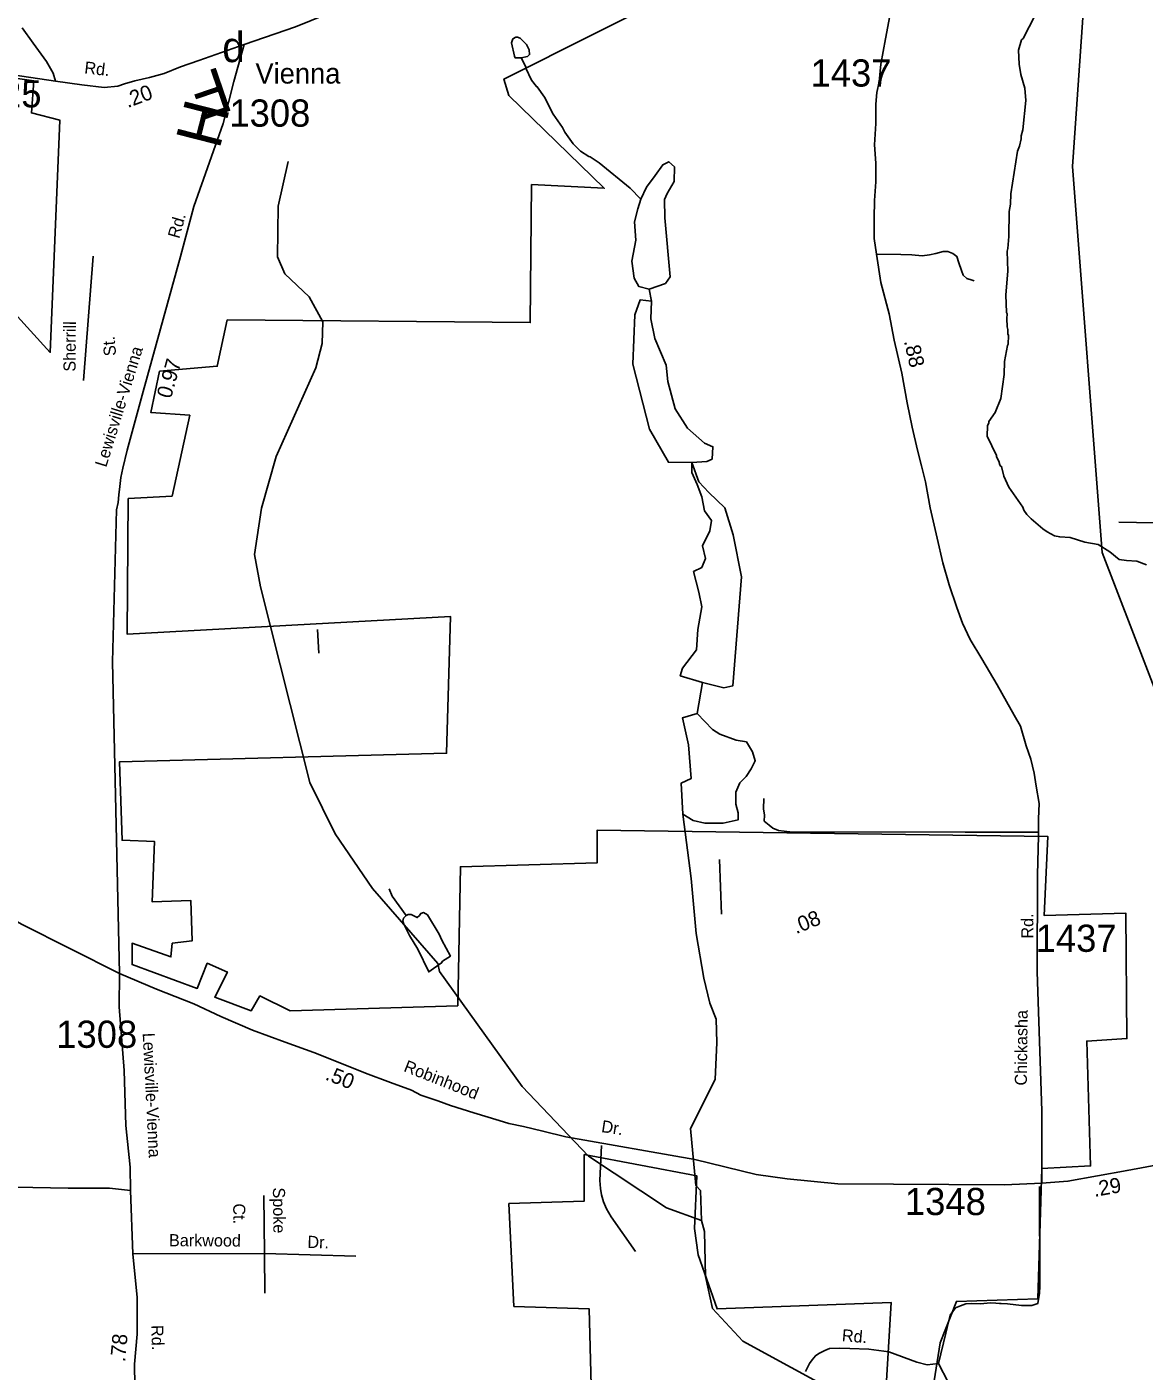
# Model space of a CAD drawing. Extents: x 1551653 to 1702041, y 811336 to 920032.
# Drawn here: x 1584838 to 1590899, y 864750 to 872044 of the extents above; entities that cross this region are included whole.
import ezdxf

# ---------------------------------------------------------------- set-up
doc = ezdxf.new("R2010")
doc.units = 0
for name, color, linetype in [('Old_Level_10', 7, 'Continuous'), ('Old_Level_11', 7, 'Continuous'), ('Old_Level_17', 7, 'Continuous'), ('Old_Level_22', 7, 'Continuous'), ('Old_Level_32', 7, 'Continuous'), ('Old_Level_35', 7, 'Continuous'), ('Old_Level_48', 7, 'Continuous'), ('Old_Level_49', 7, 'Continuous'), ('Old_Level_56', 7, 'Continuous'), ('Old_Level_59', 7, 'Continuous'), ('Old_Level_62', 7, 'Continuous'), ('Old_Level_8', 7, 'Continuous'), ('Old_Level_9', 7, 'Continuous')]:
    doc.layers.add(name, color=color, linetype=linetype)

msp = doc.modelspace()

# ---------------------------------------------------------------- linework, layer by layer
at = {"layer": 'Old_Level_32'}
for points in [[(1589631.53, 873556.503), (1589549.907, 873543.938), (1589452.588, 873515.667), (1589358.408, 873487.396), (1589251.671, 873459.125), (1589148.073, 873424.571), (1589050.754, 873393.159), (1588956.574, 873355.464), (1588906.344, 873333.475), (1588812.164, 873289.498), (1588680.312, 873229.815), (1588520.207, 873163.849), (1588247.085, 873019.352), (1587075.046, 872402.399), (1586766.222, 872241.655), (1586541.733, 872143.369), (1586294.795, 872045.084), (1586016.988, 871949.607)], [(1589524.792, 872134.153), (1589496.539, 871980.232), (1589471.424, 871841.389), (1589462.006, 871747.152), (1589449.449, 871687.469), (1589443.17, 871624.644), (1589443.17, 871520.984), (1589436.891, 871404.758), (1589443.17, 871304.238), (1589443.17, 871203.719), (1589436.891, 871103.199), (1589433.752, 871006.45), (1589433.752, 870896.507), (1589446.309, 870811.693), (1589471.424, 870657.773), (1589515.375, 870488.146), (1589543.628, 870343.649), (1589584.44, 870164.599), (1589612.694, 870004.396), (1589640.948, 869872.464), (1589669.202, 869746.815), (1589691.177, 869662.001), (1589713.152, 869575.304), (1589738.267, 869433.948), (1589775.939, 869270.604), (1589807.333, 869135.531), (1589841.865, 869016.164), (1589882.676, 868893.656), (1589914.07, 868808.843), (1589954.881, 868720.888), (1590017.874, 868614.474), (1590101.559, 868473.88), (1590152.367, 868384.141), (1590194.209, 868309.357), (1590228.003, 868249.703), (1590259.396, 868142.901), (1590284.511, 868070.653), (1590303.347, 867995.263), (1590313.76, 867923.474), (1590329.034, 867830.712), (1590326.413, 867747.814), (1590326.413, 867654.947), (1590321.169, 867442.456), (1590318.548, 866916.212), (1590343.341, 866162.929), (1590344.249, 865770.137)], [(1584812.467, 872039.529), (1584872.506, 871956.569), (1584943.98, 871856.444), (1584981.146, 871793.509), (1584992.581, 871750.598)], [(1584992.581, 871750.598), (1584393.664, 871838.227), (1584285.14, 871854.792), (1584147.187, 871875.037), (1584023.948, 871889.762), (1583922.782, 871878.719), (1583836.331, 871845.589)], [(1586016.988, 871949.607), (1585770.05, 871862.553), (1585670.491, 871826.79), (1585581.736, 871791.805), (1585503.468, 871769.884), (1585423.535, 871750.987), (1585367.054, 871734.84), (1585331.83, 871723.556), (1585256.783, 871716.001), (1585135.529, 871730.573), (1584992.581, 871750.598)], [(1585340.18, 866907.445), (1585302.146, 868599.351), (1585324.563, 869423.569), (1585332.593, 869463.914), (1585337.193, 869505.912), (1585341.758, 869549.74), (1585347.489, 869598.488), (1585358.952, 869650.104), (1585381.878, 869747.601), (1585467.852, 870065.897), (1585671.383, 870797.696), (1585743.589, 871070.118), (1585901.938, 871519.958), (1585960.866, 871747.419), (1586016.988, 871949.607)], [(1592540.685, 869172.234), (1591327.918, 869167.855), (1591294.317, 869161.873), (1591268.116, 869164.173), (1591239.647, 869167.855), (1591195.512, 869202.727), (1591160.667, 869239.925), (1591121.178, 869286.421), (1591065.428, 869330.592), (1591009.139, 869346.365), (1590953.037, 869353.366), (1590761.125, 869356.165)], [(1585340.18, 866907.445), (1584809.002, 867175.902), (1584482.046, 867364.242), (1584264.296, 867492.423), (1583970.754, 867637.718), (1583880.933, 867696.925), (1583104.211, 868113.539), (1582470.483, 868439.25), (1582201.154, 868514.025), (1581671.411, 868518.925), (1581185.495, 868552.46)], [(1585520.127, 862781.948), (1585480.764, 863151.475), (1585441.395, 863438.722), (1585414.958, 863618.062), (1585426.805, 863875.742), (1585426.805, 863963.941), (1585426.883, 864438.463), (1585421.009, 864788.322), (1585435.695, 864950.021), (1585435.695, 865149.94), (1585412.372, 865386.502), (1585400.072, 865730.182), (1585397.684, 865856.901), (1585374.243, 866082.327), (1585365.43, 866382.206), (1585338.994, 866726.185), (1585340.18, 866907.445)], [(1590344.249, 865770.137), (1590142.272, 865761.564), (1589237.766, 865766.959), (1588962.084, 865792.897), (1588793.612, 865817.655), (1588461.008, 865897.951), (1587760.88, 866022.283), (1587637.835, 866053.071), (1587531.879, 866077.017), (1587453.266, 866094.121), (1587399.546, 866110.721), (1587262.829, 866151.771), (1587135.296, 866191.711), (1587067.796, 866216.71), (1586975.723, 866247.555), (1586924.454, 866274.922), (1586810.285, 866316.751), (1586674.885, 866366.951), (1586545.386, 866420.071), (1586394.087, 866478.372), (1586239.097, 866534.571), (1586061.364, 866599.567), (1585890.467, 866674.826), (1585743.496, 866743.243), (1585541.838, 866821.923), (1585340.18, 866907.445)], [(1591826.318, 866036.569), (1591529.518, 865984.87), (1591252.717, 865930.867), (1591063.918, 865889.47), (1590991.52, 865872.57), (1590806.917, 865839.269), (1590486.019, 865779.968), (1590344.249, 865770.137)]]:
    msp.add_lwpolyline(points, dxfattribs=at)
at = {"layer": 'Old_Level_35'}
for p, q in [((1585198.009, 870800.015), (1585144.53, 870125.462)), ((1586421.957, 868645.306), (1586413.778, 868773.529)), ((1589927.465, 867675.29), (1590326.413, 867674.714)), ((1588605.434, 867228.875), (1588595.819, 867525.737)), ((1586126.428, 865388.768), (1586122.927, 865702.971)), ((1585412.372, 865386.502), (1586126.428, 865388.768)), ((1586126.428, 865388.768), (1586622.428, 865373.67)), ((1586126.428, 865388.768), (1586129.23, 865172.571))]:
    msp.add_line(p, q, dxfattribs=at)
for points in [[(1589446.309, 870811.693), (1589578.521, 870809.558), (1589638.721, 870806.76), (1589694.721, 870802.058), (1589734.62, 870807.458), (1589768.822, 870814.958), (1589809.022, 870826.359), (1589835.02, 870826.057), (1589860.82, 870815.46), (1589882.72, 870799.26), (1589894.222, 870764.958), (1589907.621, 870722.859), (1589917.319, 870696.658), (1589936.919, 870678.459), (1589966.722, 870669.86), (1589976.722, 870665.858)], [(1588835.524, 867856.864), (1588834.723, 867800.863), (1588840.323, 867766.664), (1588837.823, 867734.666), (1588865.422, 867712.366), (1588885.323, 867696.165), (1588915.021, 867683.764), (1588976.921, 867676.664), (1589927.465, 867675.29)], [(1587955.703, 865974.391), (1587946.825, 865784.568), (1587950.325, 865740.671), (1587955.824, 865706.468), (1587965.325, 865668.269), (1587982.723, 865629.87), (1588008.124, 865587.571), (1588139.324, 865399.569)], [(1585400.072, 865730.182), (1585286.584, 865743.544), (1585061.832, 865743.544), (1584581.175, 865752.452), (1584289.665, 865759.133), (1584169.501, 865759.133), (1584064.914, 865776.949), (1583973.678, 865808.127), (1583877.991, 865828.17), (1583780.079, 865834.851), (1583556.736, 865834.789), (1583552.285, 865520.781), (1583550.06, 865487.376), (1583542.332, 865476.37)], [(1590331.748, 865752.053), (1590333.875, 865211.354), (1590331.748, 865173.037), (1590322.573, 865117.126), (1590290.572, 865105.728), (1590233.91, 865107.046), (1590157.341, 865115.561), (1590114.977, 865117.062)], [(1590123.311, 865117.69), (1590065.884, 865119.819), (1590010.591, 865114.369), (1589962.319, 865117.171), (1589931.895, 865114.369), (1589902.118, 865103.726), (1589876.595, 865093.082), (1589847.653, 865053.963), (1589837.155, 865017.962), (1589823.423, 864956.843), (1589783.011, 864790.801)], [(1589783.011, 864790.801), (1589721.331, 864784.415), (1589666.03, 864799.317), (1589514.121, 864855.472), (1589406.323, 864869.071), (1589302.321, 864872.572), (1589246.323, 864875.272), (1589192.321, 864872.172), (1589166.022, 864862.572), (1589133.922, 864844.97), (1589115.621, 864833.369), (1589097.423, 864811.47), (1589083.023, 864791.772), (1589062.521, 864747.972)], [(1589783.011, 864790.801), (1589835.344, 864689.735), (1589861.74, 864593.941), (1589921.293, 864404.484), (1589902.151, 864125.619), (1589906.428, 864011.922), (1590006.393, 863794.791), (1590057.439, 863664.938), (1590063.82, 863496.768), (1590076.582, 863392.46), (1590176.216, 863285.178), (1590237.671, 863209.285), (1590316.254, 863010.556), (1590340.567, 862868.477), (1590369.936, 862772.029), (1590391.697, 862707.804)]]:
    msp.add_lwpolyline(points, dxfattribs=at)
at = {"layer": 'Old_Level_48'}
msp.add_lwpolyline([(1583701.392, 871667.226), (1584964.915, 870278.066), (1585016.322, 871538.633), (1584862.103, 871577.222), (1584876.433, 871751.032), (1584206.67, 871847.344), (1583955.379, 871865.566), (1583838.154, 871812.489), (1583701.392, 871667.226)], dxfattribs=at)
at = {"layer": 'Old_Level_49'}
for points in [[(1588412.049, 872257.625), (1587425.971, 871760.749), (1587453.173, 871672.264), (1587970.014, 871168.581), (1587575.583, 871189), (1587568.782, 870440.281), (1585925.133, 870454.707), (1585870.729, 870202.866), (1585557.904, 870175.64), (1585510.3, 869951.024), (1585721.117, 869937.411), (1585625.871, 869498.667), (1585387.853, 869485.054), (1585381.052, 868749.949), (1587135.591, 868845.24), (1587115.189, 868103.328), (1585340.248, 868055.682), (1585354.076, 867630.363), (1585530.89, 867623.556), (1585517.289, 867296.843), (1585728.106, 867303.649), (1585734.906, 867085.84), (1585626.098, 867072.227), (1585619.297, 866997.355), (1585408.481, 867072.227), (1585408.481, 866956.516), (1585762.109, 866827.192), (1585816.513, 866963.322), (1585925.321, 866915.676), (1585857.316, 866779.546), (1586054.532, 866704.675), (1586102.136, 866786.353), (1586265.348, 866704.675), (1587176.62, 866731.901)], [(1583701.392, 871667.226), (1584964.915, 870278.066), (1585016.322, 871538.633), (1584862.103, 871577.222), (1584876.433, 871751.032), (1584206.67, 871847.344), (1583955.379, 871865.566), (1583838.154, 871812.489), (1583701.392, 871667.226)], [(1587176.62, 866731.901), (1587190.222, 867487.426), (1587931.48, 867507.845), (1587931.48, 867684.815), (1590377.458, 867650.782), (1590357.056, 867221.971), (1590799.091, 867235.584), (1590805.891, 866554.931), (1590588.274, 866541.318), (1590608.729, 865863.804), (1590343.508, 865850.191), (1590323.106, 865142.312), (1589881.071, 865128.699), (1589792.664, 864904.084), (1589724.659, 864468.466)], [(1589486.64, 864454.853), (1589527.443, 865121.892), (1588582.169, 865087.86), (1588480.16, 865380.541), (1588459.759, 865523.478), (1588473.36, 865809.352), (1587861.311, 865925.063), (1587861.311, 865673.222), (1587453.279, 865659.609), (1587480.481, 865101.473), (1587888.514, 865087.86), (1587905.959, 864395.515)]]:
    msp.add_lwpolyline(points, dxfattribs=at)
at = {"layer": 'Old_Level_56'}
msp.add_lwpolyline([(1594795.417, 882224.158), (1594492.304, 881911.724), (1594314.227, 881725.829), (1594181.696, 881585.23), (1591756.719, 879036.343), (1591646.319, 875141.951), (1590597.318, 874408.75), (1590660.92, 873411.252), (1590633.821, 873059.655), (1590510.018, 871286.457), (1590671.819, 869193.062), (1591400.592, 867299.426), (1591680.416, 866598.966), (1590226.62, 861827.778), (1590099.721, 859136.383), (1590298.021, 857488.686)], dxfattribs=at)
at = {"layer": 'Old_Level_59'}
for points in [[(1586712.194, 867369.185), (1586510.525, 867665.178), (1586372.525, 867943.741), (1586104.522, 869006.219), (1586073.559, 869180.82), (1586110.571, 869432.829), (1586189.516, 869713.648), (1586405.538, 870195.11), (1586440.5, 870325.626), (1586442.55, 870443.839), (1586369.552, 870579.891), (1586237.498, 870704.05), (1586197.513, 870796.733), (1586201.511, 871072.426), (1586254.517, 871314.285)], [(1588442.593, 867423.517), (1588397.016, 867772.164), (1588387.441, 867939.89), (1588442.501, 867966.247), (1588428.138, 868148.35), (1588394.622, 868294.511), (1588473.623, 868318.471), (1588502.451, 868487.412)], [(1588497.582, 865566.572), (1588307.601, 865636.085), (1587885.604, 865917.109), (1587524.508, 866295.43), (1587075.546, 866918.378), (1587067.549, 866961.234), (1586712.194, 867369.185)], [(1588497.582, 865566.572), (1588491.533, 865730.819), (1588467.542, 865757.578), (1588438.527, 866066.797), (1588571.849, 866331.883), (1588581.425, 866533.154), (1588576.637, 866660.147), (1588543.122, 866746.406), (1588509.606, 866882.983), (1588468.927, 867124.007), (1588442.593, 867423.517)], [(1591114.559, 863734.329), (1591039.613, 863768.573), (1590719.527, 864100.142), (1590611.567, 864151.508), (1590020.607, 864193.031), (1589771.571, 864270.336), (1589498.544, 864433.455), (1589246.74, 864627.229), (1588721.602, 864912.046), (1588557.56, 865089.416), (1588518.6, 865264.121), (1588513.576, 865507.107), (1588497.582, 865566.572)]]:
    msp.add_lwpolyline(points, dxfattribs=at)
at = {"layer": 'Old_Level_62'}
msp.add_line((1588213.092, 870620.463), (1588227.412, 870556.688), dxfattribs=at)
for points in [[(1590911.66, 869124.944), (1590859.885, 869145.654), (1590804.008, 869148.32), (1590764.023, 869154.881), (1590712.555, 869195.482), (1590648.989, 869236.287), (1590577.22, 869249.205), (1590497.455, 869274.324), (1590441.476, 869276.99), (1590413.589, 869283.346), (1590373.809, 869303.852), (1590350.023, 869320.153), (1590286.662, 869375.005), (1590262.978, 869399.303), (1590247.292, 869421.449), (1590241.448, 869437.546), (1590164.758, 869546.531), (1590137.486, 869606.919), (1590126.106, 869659.002), (1590120.159, 869661.155), (1590116.263, 869667.204), (1590110.419, 869687.299), (1590098.731, 869711.393), (1590098.834, 869719.39), (1590048.084, 869824.069), (1590048.801, 869880.048), (1590057.003, 869895.94), (1590057.106, 869903.937), (1590091.657, 869951.509), (1590122.62, 870027.07), (1590140.152, 870158.816), (1590140.972, 870228.842), (1590158.094, 870314.656), (1590162.195, 870322.55), (1590162.708, 870370.533), (1590158.812, 870378.632), (1590159.119, 870402.623), (1590155.326, 870416.669), (1590153.89, 870462.703), (1590156.146, 870486.695), (1590152.25, 870494.692), (1590149.379, 870590.758), (1590158.914, 870718.608), (1590156.248, 870826.671), (1590160.452, 870842.562), (1590165.168, 870906.539), (1590166.911, 871042.488), (1590173.37, 871082.473), (1590176.036, 871138.35), (1590212.843, 871369.956), (1590223.198, 871397.741), (1590231.605, 871437.726), (1590231.81, 871453.72), (1590240.217, 871485.606), (1590258.159, 871645.341), (1590251.393, 871712.496), (1590230.99, 871786.11), (1590220.532, 871841.781), (1590217.457, 871917.856), (1590234.168, 871973.63), (1590242.268, 871981.524), (1590307.782, 872108.657)], [(1587519.176, 871876.435), (1587552.907, 871884.125), (1587565.108, 871893.967), (1587563.365, 871920.009), (1587547.781, 871948.203), (1587514.152, 871982.652), (1587500.209, 871988.804), (1587490.264, 871988.906), (1587474.065, 871979.166), (1587467.811, 871957.226), (1587482.984, 871885.047), (1587486.88, 871876.948), (1587519.176, 871876.435)], [(1587519.176, 871876.435), (1587544.295, 871828.248), (1587544.193, 871820.251), (1587575.36, 871755.864), (1587602.017, 871721.826), (1587606.938, 871719.468), (1587646.308, 871662.976), (1587693.163, 871570.292), (1587744.323, 871497.704), (1587756.011, 871473.508), (1587801.225, 871408.916), (1587840.8, 871370.469), (1587886.424, 871341.864), (1587894.421, 871339.711), (1587942.916, 871306.8), (1588110.341, 871169.005), (1588168.576, 871109.233)], [(1588168.576, 871109.233), (1588198.728, 871173.959), (1588246.607, 871238.653), (1588287.305, 871296.159), (1588320.82, 871312.931), (1588351.942, 871284.178), (1588349.548, 871205.108), (1588311.244, 871140.414), (1588296.88, 871106.868), (1588299.275, 871008.628), (1588328.002, 870687.553), (1588301.668, 870651.612), (1588213.092, 870620.463), (1588158.031, 870634.839), (1588131.697, 870680.365), (1588119.727, 870773.813), (1588141.273, 870886.428), (1588134.091, 870987.064), (1588153.243, 871056.551), (1588168.576, 871109.233)], [(1588227.412, 870556.688), (1588165.169, 870563.876), (1588136.441, 870482.409), (1588124.472, 870214.047), (1588215.442, 869861.823), (1588318.382, 869682.116), (1588445.262, 869679.72), (1588526.657, 869686.909), (1588555.385, 869698.889), (1588560.172, 869765.979), (1588514.687, 869785.148), (1588421.323, 869866.615), (1588354.292, 869972.043), (1588315.988, 870120.599), (1588306.413, 870209.255), (1588244.17, 870353.02), (1588222.624, 870460.844), (1588227.412, 870556.688)], [(1588502.451, 868487.412), (1588382.752, 868523.353), (1588394.722, 868564.087), (1588471.329, 868664.722), (1588478.511, 868774.942), (1588500.057, 868897.142), (1588483.299, 868976.214), (1588454.571, 869088.829), (1588499.918, 869111.651), (1588519.07, 869159.573), (1588502.312, 869229.059), (1588543.009, 869310.526), (1588552.585, 869365.635), (1588514.282, 869418.349), (1588499.918, 869495.024), (1588473.585, 869562.115), (1588444.857, 869626.809), (1588445.262, 869679.72)], [(1588445.262, 869679.72), (1588483.299, 869575.957), (1588538.36, 869518.451), (1588624.542, 869434.588), (1588670.028, 869288.427), (1588715.513, 869060.798), (1588667.634, 868468.243), (1588619.755, 868458.659), (1588502.451, 868487.412)], [(1588473.623, 868318.471), (1588557.411, 868232.213), (1588598.109, 868205.856), (1588686.685, 868174.707), (1588741.747, 868165.122), (1588775.262, 868110.012), (1588789.626, 868062.091), (1588768.08, 868018.961), (1588739.353, 867975.832), (1588705.837, 867942.286), (1588684.291, 867891.969), (1588684.291, 867827.274), (1588696.261, 867779.353), (1588696.261, 867741.015), (1588614.866, 867724.243), (1588516.714, 867724.243), (1588452.077, 867738.619), (1588397.016, 867772.164)], [(1586803.032, 867368.057), (1586819.949, 867326.637), (1586894.69, 867221.753)], [(1587093.283, 866974.05), (1587087.542, 866965.438), (1587017.824, 866916.635), (1586958.461, 867038.949), (1586913.35, 867113.485), (1586882.079, 867175.924), (1586878.286, 867191.918), (1586880.541, 867207.912), (1586894.69, 867221.753)], [(1586894.69, 867221.753), (1586906.686, 867227.597), (1586922.68, 867227.392), (1586954.565, 867210.988), (1586968.714, 867222.778), (1586974.763, 867232.723), (1586988.809, 867238.567), (1587010.75, 867226.264), (1587075.443, 867121.482), (1587089.079, 867089.289), (1587135.729, 867001.937), (1587093.283, 866974.05)]]:
    msp.add_lwpolyline(points, dxfattribs=at)

# ---------------------------------------------------------------- texts
at = {"layer": 'Old_Level_10'}
for s, height, rotation, p in [('Sherrill', 65.6166, 89.6326333, (1585101.919, 870173.387)), ('St.', 65.6167, 94.6301389, (1585322.174, 870260.547)), ('Spoke', 65.6167, 270.6383278, (1586172.49, 865746.2)), ('Ct.', 65.6167, 270.6383278, (1585956.893, 865659.699)), ('Barkwood', 65.6167, 359.6893, (1585608.7, 865427.835)), ('Dr.', 65.6167, 358.2564361, (1586359.038, 865419.316)), ('Rd.', 65.6167, 355.2065694, (1589257.541, 864912.881))]:
    msp.add_text(s, height=height, rotation=rotation, dxfattribs=at).set_placement(p)
at = {"layer": 'Old_Level_11'}
for s, height, rotation, p in [('Rd.', 65.6167, 353.5933222, (1585147.298, 871792.371)), ('Rd.', 65.6167, 74.1085722, (1585663.761, 870892.269)), ('Lewisville-Vienna', 65.61666, 72.8297611, (1585267.975, 869651.12)), ('Rd.', 65.6167, 90.0014694, (1590298.192, 867097.056)), ('Chickasha', 65.6167, 89.3903139, (1590262.973, 866299.466)), ('Lewisville-Vienna', 65.61666, 272.857725, (1585465.909, 866584.26)), ('Robinhood', 65.6167, 338.3469722, (1586877.659, 866378.779)), ('Dr.', 65.6167, 351.2612028, (1587951.385, 866047.831)), ('Rd.', 65.6167, 271.9642111, (1585512.044, 864999.105))]:
    msp.add_text(s, height=height, rotation=rotation, dxfattribs=at).set_placement(p)
at = {"layer": 'Old_Level_17'}
for s, rotation, p in [('.20', 20.7839694, (1585385.002, 871603.408)), ('.88', 282.8403472, (1589595.81, 870338.745)), ('0.97', 74.4574667, (1585619.49, 870023.724)), ('.08', 22.0652389, (1589011.2, 867120.871)), ('.50', 338.3246694, (1586451.766, 866333.63)), ('.29', 10.2256111, (1590630.105, 865694.989)), ('.78', 84.8102361, (1585371.08, 864797.379))]:
    msp.add_text(s, height=82.0208, rotation=rotation, dxfattribs=at).set_placement(p)
at = {"layer": 'Old_Level_22'}
for s, rotation, p in [('F', 198.8978472, (1585888.184, 871831.394)), ('H', 75.7292806, (1585882.011, 871374.61))]:
    msp.add_text(s, height=246.062, rotation=rotation, dxfattribs=at).set_placement(p)
at = {"layer": 'Old_Level_8'}
for s, p in [('1437', (1589089.226, 871720.39)), ('1525', (1584478.176, 871607.417)), ('1308', (1585936.429, 871502.943)), ('1437', (1590310.851, 867025.291)), ('1308', (1584997.015, 866504.351)), ('1348', (1589601.328, 865596.652))]:
    msp.add_text(s, height=147.6375, dxfattribs=at).set_placement(p)
at = {"layer": 'Old_Level_9'}
for s, height, p in [('d', 164.042, (1585897.889, 871853.282)), ('Vienna', 110.7281, (1586077.798, 871736.749))]:
    msp.add_text(s, height=height, dxfattribs=at).set_placement(p)

doc.saveas('drawing.dxf')
